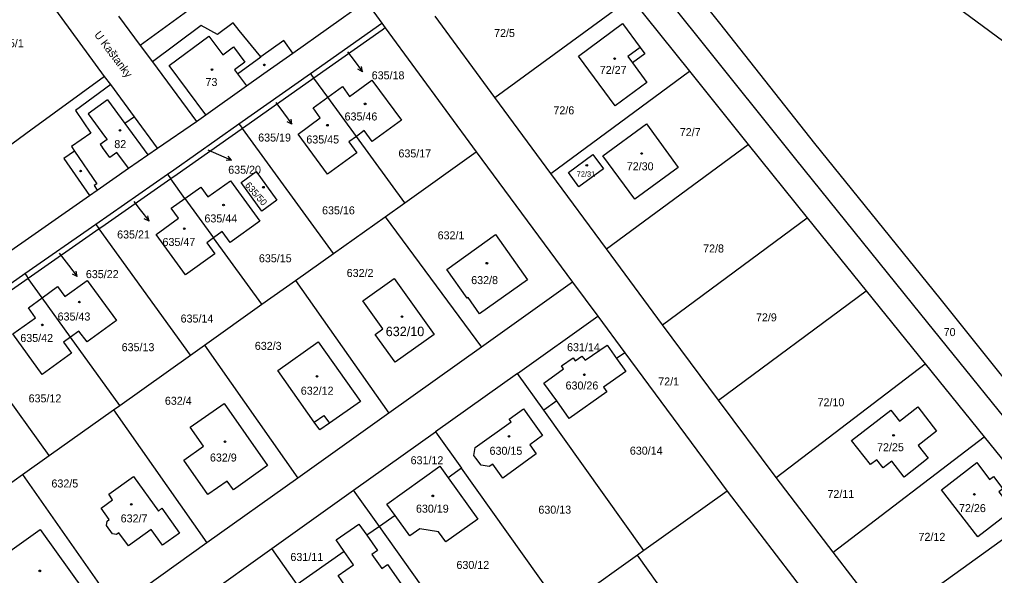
# Model space of a CAD drawing. Extents: x -724107 to -720612, y -1045267 to -1038441.
# Drawn here: x -723235.3 to -723028.3, y -1042742.2 to -1042624.1 of the extents above; entities that cross this region are included whole.
import ezdxf

# ---------------------------------------------------------------- set-up
doc = ezdxf.new("R2010")
doc.units = 0
for name, color, linetype in [('Hranice parcel', 7, 'Continuous'), ('Parcelní čísla', 7, 'Continuous'), ('Pop  PČ popisy', 7, 'Continuous'), ('Vnitřní kresba', 7, 'Continuous'), ('Značky budov', 7, 'Continuous')]:
    doc.layers.add(name, color=color, linetype=linetype)

msp = doc.modelspace()

# ---------------------------------------------------------------- linework, layer by layer
at = {"layer": 'Hranice parcel'}
for p, q in [((-723217.23, -1042636.16), (-723235.6, -1042610.97)), ((-723193.45, -1042617.73), (-723209.7, -1042629.56)), ((-723161.78, -1042620.17), (-723158.38, -1042624.81)), ((-723134.38, -1042640.64), (-723105.47, -1042619.44)), ((-723105.47, -1042619.44), (-723093, -1042635.02)), ((-723214.27, -1042623.35), (-723209.7, -1042629.56)), ((-723134.38, -1042640.64), (-723147.07, -1042623.33)), ((-723173.54, -1042635.51), (-723158.38, -1042624.81)), ((-723158.38, -1042624.81), (-723157.64, -1042625.82)), ((-723157.64, -1042625.82), (-723138.31, -1042652.19)), ((-723209.7, -1042629.56), (-723207.08, -1042633.08)), ((-723207.08, -1042633.08), (-723197.7, -1042645.72)), ((-723188.71, -1042646.22), (-723173.54, -1042635.51)), ((-723122.48, -1042656.8), (-723093, -1042635.02)), ((-723093, -1042635.02), (-723080.56, -1042650.62)), ((-723215.94, -1042637.9), (-723217.23, -1042636.16)), ((-723169.87, -1042640.57), (-723172.82, -1042636.53)), ((-723163.78, -1042648.91), (-723169.87, -1042640.57)), ((-723122.48, -1042656.8), (-723134.38, -1042640.64)), ((-723206, -1042651.38), (-723197.7, -1042645.72)), ((-723168.65, -1042673.79), (-723187.99, -1042647.24)), ((-723153.49, -1042663), (-723163.78, -1042648.91)), ((-723153.49, -1042663), (-723138.31, -1042652.19)), ((-723138.31, -1042652.19), (-723117.87, -1042679.88)), ((-723110.63, -1042672.83), (-723080.56, -1042650.62)), ((-723080.56, -1042650.62), (-723068.07, -1042666.18)), ((-723219.12, -1042667.54), (-723203.9, -1042656.93)), ((-723200.18, -1042662.08), (-723203.18, -1042657.95)), ((-723110.63, -1042672.83), (-723122.48, -1042656.8)), ((-723247.04, -1042680.03), (-723220.42, -1042661.45)), ((-723200.18, -1042662.08), (-723194.08, -1042670.48)), ((-723157.68, -1042665.98), (-723153.49, -1042663)), ((-723168.65, -1042673.79), (-723157.68, -1042665.98)), ((-723157.68, -1042665.98), (-723137.22, -1042693.69)), ((-723098.74, -1042688.94), (-723068.07, -1042666.18)), ((-723068.07, -1042666.18), (-723055.55, -1042681.72)), ((-723234.18, -1042678.05), (-723219.12, -1042667.54)), ((-723218.4, -1042668.57), (-723233.46, -1042679.08)), ((-723199.01, -1042695.41), (-723218.4, -1042668.57)), ((-723183.82, -1042684.59), (-723194.08, -1042670.48)), ((-723098.74, -1042688.94), (-723110.63, -1042672.83)), ((-723176.69, -1042679.51), (-723168.65, -1042673.79)), ((-723230.49, -1042683.2), (-723233.46, -1042679.08)), ((-723183.82, -1042684.59), (-723176.69, -1042679.51)), ((-723176.69, -1042679.51), (-723156.89, -1042707.73)), ((-723117.87, -1042679.88), (-723137.22, -1042693.69)), ((-723117.87, -1042679.88), (-723112.52, -1042687.12)), ((-723224.46, -1042691.57), (-723230.49, -1042683.2)), ((-723086.87, -1042704.95), (-723055.55, -1042681.72)), ((-723055.55, -1042681.72), (-723043.02, -1042697.24)), ((-723196.03, -1042693.29), (-723183.82, -1042684.59)), ((-723129.56, -1042699.28), (-723112.52, -1042687.12)), ((-723112.52, -1042687.12), (-723106.78, -1042694.88)), ((-723086.87, -1042704.95), (-723098.74, -1042688.94)), ((-723228.99, -1042716.75), (-723248.46, -1042689.69)), ((-723214, -1042706.08), (-723224.46, -1042691.57)), ((-723199.01, -1042695.41), (-723196.03, -1042693.29)), ((-723196.03, -1042693.29), (-723176.23, -1042721.53)), ((-723137.22, -1042693.69), (-723156.89, -1042707.73)), ((-723214, -1042706.08), (-723199.01, -1042695.41)), ((-723106.78, -1042694.88), (-723108.51, -1042696.11)), ((-723106.78, -1042694.88), (-723085.01, -1042724.34)), ((-723074.64, -1042721.44), (-723043.02, -1042697.24)), ((-723043.02, -1042697.24), (-723030.47, -1042712.76)), ((-723129.56, -1042699.28), (-723146.95, -1042711.69)), ((-723124, -1042707.09), (-723129.56, -1042699.28)), ((-723215.36, -1042707.05), (-723214, -1042706.08)), ((-723121.24, -1042705.13), (-723124, -1042707.09)), ((-723074.64, -1042721.44), (-723086.87, -1042704.95)), ((-723228.99, -1042716.75), (-723215.36, -1042707.05)), ((-723215.36, -1042707.05), (-723195.54, -1042735.31)), ((-723156.89, -1042707.73), (-723176.23, -1042721.53)), ((-723102.73, -1042736.95), (-723124, -1042707.09)), ((-723164.35, -1042724.1), (-723146.95, -1042711.69)), ((-723146.95, -1042711.69), (-723141.43, -1042719.44)), ((-723062.52, -1042737.28), (-723030.47, -1042712.76)), ((-723030.47, -1042712.76), (-723017.94, -1042728.33)), ((-723234.67, -1042720.79), (-723228.99, -1042716.75)), ((-723141.43, -1042719.44), (-723144.28, -1042721.46)), ((-723120.15, -1042749.35), (-723141.43, -1042719.44)), ((-723243.99, -1042727.43), (-723234.67, -1042720.79)), ((-723234.67, -1042720.79), (-723214.83, -1042749.08)), ((-723176.23, -1042721.53), (-723195.54, -1042735.31)), ((-723062.52, -1042737.28), (-723074.64, -1042721.44)), ((-723181.76, -1042736.52), (-723164.35, -1042724.1)), ((-723158.87, -1042731.8), (-723164.35, -1042724.1)), ((-723085.01, -1042724.34), (-723102.73, -1042736.95)), ((-723085.01, -1042724.34), (-723065.3, -1042750.1)), ((-723051.16, -1042752.31), (-723017.94, -1042728.33)), ((-723155.57, -1042729.46), (-723158.87, -1042731.8)), ((-723158.87, -1042731.8), (-723161.54, -1042733.69)), ((-723137.57, -1042761.75), (-723158.87, -1042731.8)), ((-723195.54, -1042735.31), (-723214.83, -1042749.08)), ((-723199.18, -1042748.95), (-723181.76, -1042736.52)), ((-723176.32, -1042744.17), (-723181.76, -1042736.52)), ((-723166.38, -1042737.13), (-723176.32, -1042744.17)), ((-723102.73, -1042736.95), (-723104.11, -1042737.93)), ((-723104.11, -1042737.93), (-723120.15, -1042749.35)), ((-723085.21, -1042764.14), (-723104.11, -1042737.93))]:
    msp.add_line(p, q, dxfattribs=at)
for points in [[(-722899.6, -1042738.39), (-722941.72, -1042691.23), (-723134.87, -1042548.63)], [(-723144.12, -1042553.98), (-723118.34, -1042585.2), (-723086.65, -1042624.83), (-723066.46, -1042650.43), (-723039.88, -1042683.34), (-723014.05, -1042715.66), (-722976.35, -1042762.64), (-722937.34, -1042811.96)], [(-723148.19, -1042556.33), (-723122.67, -1042588.56), (-723090.95, -1042628.16), (-723070.53, -1042653.76), (-723043.99, -1042686.69), (-723017.98, -1042718.84), (-722980.48, -1042765.97), (-722941.81, -1042813.99), (-722937.16, -1042827.15)], [(-723177.25, -1042631.19), (-723162.15, -1042620.43), (-723161.78, -1042620.17)], [(-723177.25, -1042631.19), (-723179.18, -1042628.5), (-723184.07, -1042632.02), (-723188.68, -1042626.4), (-723189.92, -1042624.74), (-723193.24, -1042627.22), (-723196.7, -1042625.35), (-723207.08, -1042633.08)], [(-723103.5, -1042630.02), (-723102.54, -1042631.35), (-723105.15, -1042633.27), (-723102.11, -1042637.46), (-723108.79, -1042642.39), (-723116.59, -1042631.87), (-723107.26, -1042624.93), (-723103.5, -1042630.02)], [(-723157.64, -1042625.82), (-723158.33, -1042626.31), (-723172.82, -1042636.53)], [(-723197.7, -1042645.72), (-723195.71, -1042644.3), (-723187.08, -1042638.18), (-723183.4, -1042635.57), (-723177.25, -1042631.19)], [(-723173.54, -1042635.51), (-723173.29, -1042635.87), (-723172.94, -1042636.36), (-723172.82, -1042636.53)], [(-723217.23, -1042636.16), (-723232.9, -1042647.61), (-723248.57, -1042659.06)], [(-723172.82, -1042636.53), (-723187.73, -1042647.06), (-723187.99, -1042647.24)], [(-723169.87, -1042640.57), (-723166.74, -1042638.29), (-723165.2, -1042640.41), (-723160.46, -1042636.93), (-723154.17, -1042645.49), (-723160.41, -1042650.01), (-723162.11, -1042647.68), (-723163.78, -1042648.91)], [(-723215.94, -1042637.9), (-723223.43, -1042643.42), (-723220.16, -1042648.2), (-723224.3, -1042651.08), (-723223.64, -1042652.04), (-723225.87, -1042653.57), (-723220.42, -1042661.45)], [(-723206, -1042651.38), (-723210.89, -1042644.75), (-723215.94, -1042637.9)], [(-723163.78, -1042648.91), (-723165.39, -1042650.08), (-723163.7, -1042652.4), (-723169.9, -1042656.95), (-723176.15, -1042648.44), (-723171.43, -1042644.94), (-723172.96, -1042642.83), (-723169.87, -1042640.57)], [(-723203.9, -1042656.93), (-723202.56, -1042655.99), (-723188.71, -1042646.22)], [(-723187.99, -1042647.24), (-723188.23, -1042647.41), (-723201.84, -1042657.01), (-723203.18, -1042657.95)], [(-723188.71, -1042646.22), (-723188.47, -1042646.57), (-723187.99, -1042647.24)], [(-723104.67, -1042662.28), (-723111.43, -1042653.02), (-723102.17, -1042646.27), (-723095.41, -1042655.54), (-723104.67, -1042662.28)], [(-723220.42, -1042661.45), (-723218.8, -1042660.32), (-723212.16, -1042655.68), (-723208.04, -1042652.8), (-723206, -1042651.38)], [(-723118.75, -1042656.58), (-723113.56, -1042652.75), (-723111.33, -1042655.77), (-723116.5, -1042659.59), (-723118.75, -1042656.58)], [(-723183.82, -1042664.8), (-723188.21, -1042658.7), (-723185.03, -1042656.38), (-723180.64, -1042662.44), (-723183.82, -1042664.8)], [(-723203.18, -1042657.95), (-723217.82, -1042668.17), (-723218.4, -1042668.57)], [(-723203.9, -1042656.93), (-723203.73, -1042657.17), (-723203.39, -1042657.65), (-723203.18, -1042657.95)], [(-723200.18, -1042662.08), (-723196.84, -1042659.67), (-723195.32, -1042661.78), (-723190.52, -1042658.33), (-723184.28, -1042666.91), (-723190.6, -1042671.43), (-723192.26, -1042669.12), (-723194.08, -1042670.48)], [(-723194.08, -1042670.48), (-723195.5, -1042671.55), (-723193.83, -1042673.88), (-723200.08, -1042678.31), (-723206.31, -1042669.76), (-723201.53, -1042666.3), (-723203.09, -1042664.19), (-723200.18, -1042662.08)], [(-723219.12, -1042667.54), (-723218.87, -1042667.9), (-723218.4, -1042668.57)], [(-723144.6, -1042677.17), (-723134.22, -1042669.77), (-723127.42, -1042679.36), (-723137.6, -1042686.61), (-723140.07, -1042683.18), (-723140.26, -1042683.32), (-723144.6, -1042677.17)], [(-723249.19, -1042688.68), (-723243.67, -1042684.69), (-723234.18, -1042678.05)], [(-723233.46, -1042679.08), (-723242.95, -1042685.71), (-723248.46, -1042689.69)], [(-723234.18, -1042678.05), (-723233.85, -1042678.53), (-723233.46, -1042679.08)], [(-723155.56, -1042696.89), (-723159.77, -1042690.99), (-723158.14, -1042689.83), (-723162.39, -1042683.84), (-723155.78, -1042679.11), (-723147.29, -1042690.98), (-723155.56, -1042696.89)], [(-723230.49, -1042683.2), (-723227.22, -1042680.83), (-723225.69, -1042682.95), (-723220.91, -1042679.53), (-723214.71, -1042688.06), (-723220.93, -1042692.58), (-723222.69, -1042690.3), (-723224.46, -1042691.57)], [(-723224.46, -1042691.57), (-723225.94, -1042692.62), (-723224.3, -1042694.95), (-723230.47, -1042699.51), (-723236.72, -1042690.88), (-723231.89, -1042687.48), (-723233.43, -1042685.32), (-723230.49, -1042683.2)], [(-723171.54, -1042711.31), (-723172.71, -1042709.64), (-723180.45, -1042698.64), (-723171.87, -1042692.58), (-723162.92, -1042705.27), (-723169.47, -1042709.87), (-723171.54, -1042711.31)], [(-723121.24, -1042705.13), (-723123.94, -1042701.33), (-723119.8, -1042698.34), (-723120.24, -1042697.66), (-723117.73, -1042695.95), (-723117.28, -1042696.61), (-723115.9, -1042695.59), (-723115.22, -1042696.5), (-723110.51, -1042693.25), (-723108.51, -1042696.11)], [(-723108.51, -1042696.11), (-723106.58, -1042698.87), (-723111.33, -1042702.19), (-723110.6, -1042703.23), (-723118.56, -1042708.89), (-723121.24, -1042705.13)], [(-723200.43, -1042717.69), (-723196.25, -1042714.78), (-723199.07, -1042710.73), (-723191.82, -1042705.68), (-723182.63, -1042718.89), (-723189.88, -1042724.04), (-723191.19, -1042722.18), (-723195.33, -1042725.02), (-723200.43, -1042717.69)], [(-723138.39, -1042717.29), (-723138.8, -1042716.73), (-723138.52, -1042715.03), (-723130.89, -1042709.55), (-723131.3, -1042708.98), (-723128.29, -1042706.81), (-723126.72, -1042709.02), (-723124.26, -1042712.48), (-723126.97, -1042714.43), (-723125.56, -1042716.38), (-723132.68, -1042721.57), (-723134.83, -1042718.55), (-723135.61, -1042719.1), (-723137.29, -1042718.78), (-723138.39, -1042717.29)], [(-723044.5, -1042714.57), (-723042.38, -1042717.33), (-723047.46, -1042721.35), (-723050.04, -1042717.96), (-723051.9, -1042719.38), (-723053.22, -1042717.62), (-723054.59, -1042718.64), (-723058.61, -1042713.53), (-723050.29, -1042707.09), (-723048.45, -1042709.46), (-723044.51, -1042706.41), (-723040.55, -1042711.53), (-723044.5, -1042714.57)], [(-723029.33, -1042721.84), (-723028.5, -1042721.21), (-723026.5, -1042723.83), (-723027.32, -1042724.45), (-723024.35, -1042728.31), (-723031.78, -1042734.04), (-723039.51, -1042724.02), (-723032.01, -1042718.25), (-723029.33, -1042721.84)], [(-723155.57, -1042729.46), (-723157.29, -1042727.05), (-723146.03, -1042719.02), (-723144.28, -1042721.46)], [(-723215.54, -1042726.15), (-723216.36, -1042724.95), (-723211.11, -1042721.2), (-723205.83, -1042728.53), (-723205.07, -1042727.92), (-723201.34, -1042733.22), (-723204.92, -1042735.82), (-723207.35, -1042732.46), (-723212.2, -1042735.96), (-723214.23, -1042733.17), (-723214.7, -1042733.53), (-723215.59, -1042733.39), (-723216.87, -1042731.6), (-723216.69, -1042730.67), (-723216.24, -1042730.34), (-723217.99, -1042727.91), (-723215.54, -1042726.15)], [(-723144.28, -1042721.46), (-723138, -1042730.28), (-723144.78, -1042735.11), (-723146.3, -1042732.98), (-723150.31, -1042732.3), (-723152.45, -1042733.83), (-723155.57, -1042729.46)], [(-723221.45, -1042745.68), (-723226.88, -1042749.54), (-723229.12, -1042746.38), (-723230.22, -1042747.17), (-723229.92, -1042747.58), (-723232.78, -1042749.62), (-723233.09, -1042749.2), (-723235.63, -1042751), (-723237.58, -1042748.27), (-723239, -1042749.27), (-723242.78, -1042743.99), (-723241.36, -1042742.95), (-723242.36, -1042741.54), (-723240.95, -1042740.53), (-723241.38, -1042739.92), (-723230.89, -1042732.44), (-723221.45, -1042745.68)], [(-723166.38, -1042737.13), (-723168.1, -1042734.67), (-723163.22, -1042731.29), (-723161.54, -1042733.69)], [(-723161.54, -1042733.69), (-723159.27, -1042736.91), (-723160.5, -1042737.78), (-723158.39, -1042740.77), (-723157.16, -1042739.91), (-723152.33, -1042746.78), (-723161.66, -1042753.34), (-723166.5, -1042746.5), (-723165.28, -1042745.61), (-723167.65, -1042742.24), (-723164.39, -1042739.98), (-723166.38, -1042737.13)], [(-723051.16, -1042752.31), (-723053.64, -1042748.87), (-723062.52, -1042737.28)]]:
    msp.add_lwpolyline(points, dxfattribs=at)
at = {"layer": 'Pop  PČ popisy'}
for p, q in [((-723165.63, -1042630.91), (-723164.26, -1042632.75)), ((-723164.26, -1042632.75), (-723162.45, -1042635.15)), ((-723162.45, -1042635.15), (-723163.46, -1042634.65)), ((-723162.45, -1042635.15), (-723162.66, -1042634.05)), ((-723180.86, -1042641.71), (-723179.23, -1042643.91)), ((-723179.23, -1042643.91), (-723177.47, -1042646.34)), ((-723177.47, -1042646.34), (-723178.46, -1042645.82)), ((-723177.47, -1042646.34), (-723177.65, -1042645.23)), ((-723195.32, -1042651.77), (-723193.04, -1042652.77)), ((-723193.04, -1042652.77), (-723190.3, -1042653.99)), ((-723190.3, -1042653.99), (-723191.42, -1042654.04)), ((-723190.3, -1042653.99), (-723191.01, -1042653.13)), ((-723211.05, -1042662.72), (-723209.66, -1042664.52)), ((-723209.66, -1042664.52), (-723207.81, -1042666.89)), ((-723207.81, -1042666.89), (-723208.82, -1042666.4)), ((-723207.81, -1042666.89), (-723208.03, -1042665.79)), ((-723226.91, -1042673.73), (-723224.9, -1042676.3)), ((-723224.9, -1042676.3), (-723223.05, -1042678.67)), ((-723223.05, -1042678.67), (-723224.06, -1042678.18)), ((-723223.05, -1042678.67), (-723223.27, -1042677.57))]:
    msp.add_line(p, q, dxfattribs=at)
at = {"layer": 'Vnitřní kresba'}
for p, q in [((-723203.5, -1042633.83), (-723195.11, -1042627.59)), ((-723195.11, -1042627.59), (-723192.1, -1042631.55)), ((-723192.1, -1042631.55), (-723189.85, -1042629.87)), ((-723189.85, -1042629.87), (-723187.44, -1042633.1)), ((-723103.5, -1042630.02), (-723106.14, -1042631.95)), ((-723187.44, -1042633.1), (-723189.66, -1042634.75)), ((-723189.03, -1042635.59), (-723184.07, -1042632.02)), ((-723106.14, -1042631.95), (-723105.15, -1042633.27)), ((-723195.71, -1042644.3), (-723203.5, -1042633.83)), ((-723189.66, -1042634.75), (-723189.03, -1042635.59)), ((-723189.03, -1042635.59), (-723187.08, -1042638.18)), ((-723216.64, -1042641.13), (-723220.7, -1042644.12)), ((-723216.64, -1042641.13), (-723212.93, -1042646.17)), ((-723220.7, -1042644.12), (-723217.02, -1042649.12)), ((-723210.89, -1042644.75), (-723212.93, -1042646.17)), ((-723212.93, -1042646.17), (-723208.04, -1042652.8)), ((-723216.69, -1042649.57), (-723218.18, -1042650.66)), ((-723217.02, -1042649.12), (-723216.69, -1042649.57)), ((-723223.64, -1042652.04), (-723218.92, -1042658.96)), ((-723218.18, -1042650.66), (-723217.71, -1042651.29)), ((-723216.13, -1042653.42), (-723217.71, -1042651.29)), ((-723214.66, -1042652.32), (-723216.13, -1042653.42)), ((-723212.16, -1042655.68), (-723214.66, -1042652.32)), ((-723218.92, -1042658.96), (-723219.48, -1042659.35)), ((-723219.48, -1042659.35), (-723218.8, -1042660.32)), ((-723172.71, -1042709.64), (-723170.66, -1042708.21)), ((-723170.66, -1042708.21), (-723169.47, -1042709.87))]:
    msp.add_line(p, q, dxfattribs=at)
at = {"layer": 'Značky budov'}
for centre in [(-723183.31, -1042633.71), (-723108.94, -1042632.38), (-723194.43, -1042634.7), (-723161.92, -1042641.99), (-723213.98, -1042647.62), (-723169.91, -1042646.53), (-723103.2, -1042652.54), (-723222.34, -1042656.27), (-723114.84, -1042655.07), (-723183.5, -1042659.7), (-723191.98, -1042663.49), (-723200.32, -1042668.52), (-723136.06, -1042675.86), (-723222.59, -1042684.12), (-723154.1, -1042687.21), (-723230.47, -1042688.97), (-723172.13, -1042699.91), (-723115.35, -1042699.58), (-723049.71, -1042712.45), (-723191.67, -1042713.8), (-723131.37, -1042712.66), (-723147.55, -1042725.31), (-723032.54, -1042725), (-723211.57, -1042727.11), (-723231.01, -1042741.25)]:
    msp.add_circle(centre, 0.175, dxfattribs=at)

# ---------------------------------------------------------------- texts
at = {"layer": 'Parcelní čísla'}
for s, height, p in [('72/5', 1.7, (-723134.53, -1042627.78)), ('85/1', 1.7, (-723238.83, -1042629.96)), ('635/18', 1.7, (-723160.52, -1042636.77)), ('72/27', 1.7, (-723112.09, -1042635.63)), ('73', 1.7, (-723195.82, -1042638.19)), ('635/46', 1.7, (-723166.28, -1042645.52)), ('72/6', 1.7, (-723121.93, -1042644.21)), ('72/7', 1.7, (-723095.1, -1042648.85)), ('82', 1.7, (-723215.18, -1042651.39)), ('635/19', 1.7, (-723184.62, -1042650)), ('635/45', 1.7, (-723174.4, -1042650.41)), ('635/17', 1.7, (-723154.84, -1042653.37)), ('72/30', 1.7, (-723106.35, -1042656.11)), ('635/20', 1.7, (-723190.99, -1042656.84)), ('72/31', 1.139, (-723116.99, -1042657.47)), ('635/16', 1.7, (-723171.06, -1042665.47)), ('635/44', 1.7, (-723196.04, -1042667.19)), ('635/21', 1.7, (-723214.58, -1042670.6)), ('635/47', 1.7, (-723204.94, -1042672.19)), ('632/1', 1.7, (-723146.52, -1042670.78)), ('72/8', 1.7, (-723090.14, -1042673.58)), ('635/15', 1.7, (-723184.47, -1042675.66)), ('632/2', 1.7, (-723165.83, -1042678.78)), ('635/22', 1.7, (-723221.22, -1042679.03)), ('632/8', 1.7, (-723139.39, -1042680.3)), ('635/43', 1.7, (-723227.22, -1042688.04)), ('635/14', 1.7, (-723201.1, -1042688.47)), ('72/9', 1.7, (-723078.92, -1042688.22)), ('632/10', 2, (-723157.54, -1042691.36)), ('635/42', 1.7, (-723235.14, -1042692.6)), ('70', 1.7, (-723039.06, -1042691.35)), ('635/13', 1.7, (-723213.62, -1042694.56)), ('632/3', 1.7, (-723185.34, -1042694.28)), ('631/14', 1.7, (-723119.03, -1042694.56)), ('632/12', 1.7, (-723175.58, -1042703.81)), ('630/26', 1.7, (-723119.35, -1042702.7)), ('72/1', 1.7, (-723099.67, -1042701.84)), ('635/12', 1.7, (-723233.38, -1042705.44)), ('632/4', 1.7, (-723204.44, -1042705.95)), ('72/10', 1.7, (-723065.84, -1042706.27)), ('72/25', 1.7, (-723053.2, -1042715.82)), ('632/9', 1.7, (-723194.87, -1042718.01)), ('630/15', 1.7, (-723135.49, -1042716.58)), ('630/14', 1.7, (-723105.7, -1042716.55)), ('631/12', 1.7, (-723152.26, -1042718.59)), ('632/5', 1.7, (-723228.53, -1042723.53)), ('72/11', 1.7, (-723063.74, -1042725.76)), ('630/19', 1.7, (-723151.12, -1042728.88)), ('630/13', 1.7, (-723125.12, -1042729.1)), ('72/26', 1.7, (-723035.8, -1042728.76)), ('632/7', 1.7, (-723213.83, -1042730.95)), ('72/12', 1.7, (-723044.4, -1042734.87)), ('631/11', 1.7, (-723177.78, -1042739.15)), ('630/12', 1.7, (-723142.52, -1042740.84))]:
    msp.add_text(s, height=height, dxfattribs=at).set_placement(p)
msp.add_text('635/50', height=1.436, rotation=311, dxfattribs=at).set_placement((-723187.53, -1042659.35))
at = {"layer": 'Pop  PČ popisy'}
msp.add_text('U Kaštanky', height=1.7, rotation=307, dxfattribs=at).set_placement((-723219.54, -1042627.32))

doc.saveas('drawing.dxf')
